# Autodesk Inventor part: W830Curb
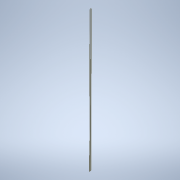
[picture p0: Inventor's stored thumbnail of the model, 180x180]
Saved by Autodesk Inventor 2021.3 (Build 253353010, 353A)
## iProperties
Created: 2021-10
Part Number: W830Curb
Material: Concrete, Cast-in-Place, Gray
Document SubType Name: Modeling
Designer: u1426
Density: 2.40731 g/cm^3
Appearance: Flat - Gray 1
Author: u1426
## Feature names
1. Sweep1
2. Sweep3
## Parameters: d10 = 1016 mm, d43 = 0, d44 = 0, d45 = 0, d59 = 12.7 mm, d63 = 12.7 mm, d126 = 508 mm, d127 = 152.4 mm, d128 = 19.05 mm, d129 = 50.8 mm, d132 = 279.4 mm, d133 = 279.4 mm, d138 = 152.4 mm, d139 = 76.2 mm, d140 = 101.6 mm, d145 = 349.25 mm, d146 = 6.35 mm, d147 = 6.35 mm, d148 = 12.7 mm, d149 = 6.35 mm, d150 = 12.7 mm, d151 = 6.35 mm, d152 = 19.05 mm, d153 = 19.05 mm, d154 = 19.05 mm, d155 = 19.05 mm, d158 = 0, d159 = 0, d160 = 64414.4 mm, d161 = 257.6576 mm, d164 = 31.75 mm, d165 = 31.75 mm
